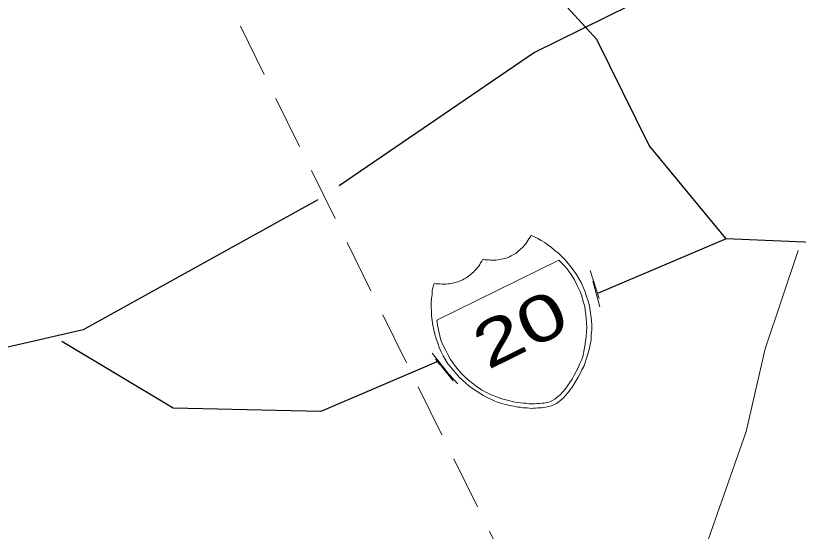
# Model space of a CAD drawing. Extents: x 2356606 to 2371222, y 6973096 to 6982644.
# Drawn here: x 2370773.7 to 2370861.3, y 6980289.2 to 6980347 of the extents above; entities that cross this region are included whole.
import ezdxf

# ---------------------------------------------------------------- set-up
doc = ezdxf.new("R2010")
doc.units = 0
doc.header["$LTSCALE"] = 2
doc.linetypes.add('MEDIUM_DASHED', pattern=[4.5, 3, -1.5])
doc.layers.add('62', color=7, linetype='Continuous', lineweight=13)
doc.layers.add('63', color=7, linetype='Continuous', lineweight=13)

msp = doc.modelspace()

# ---------------------------------------------------------------- linework, layer by layer
at = {"layer": '62', "linetype": 'MEDIUM_DASHED'}
msp.add_line((2370774.944, 6980394.196), (2370857.153, 6980227.678), dxfattribs=at)
at = {"layer": '62', "lineweight": 25}
msp.add_line((2370853.225, 6980321.969), (2370838.852, 6980315.852), dxfattribs=at)
at = {"layer": '62'}
for p, q in [((2370838.029, 6980318.432), (2370839.029, 6980315.29)), ((2370838.314, 6980317.245), (2370839.095, 6980314.393)), ((2370820.312, 6980309.186), (2370822.081, 6980306.974)), ((2370820.701, 6980308.55), (2370822.689, 6980306.095)), ((2370820.808, 6980308.329), (2370823.189, 6980305.741))]:
    msp.add_line(p, q, dxfattribs=at)
at = {"layer": '62', "lineweight": 25}
for points in [[(2371011.483, 6980396.661), (2371005.138, 6980391.825), (2370996.569, 6980386.616), (2370984.445, 6980379.452), (2370975.486, 6980375.033), (2370969.457, 6980371.078), (2370966.224, 6980366.347), (2370958.11, 6980360.159), (2370945.05, 6980354.893), (2370933.131, 6980350.014), (2370920.141, 6980344.556), (2370901.53, 6980332.234), (2370881.498, 6980325.485), (2370864.621, 6980321.497), (2370853.225, 6980321.969), (2370844.613, 6980332.451), (2370838.758, 6980344.313), (2370834.175, 6980349.329), (2370834.503, 6980359.904)], [(2370856.753, 6980352.442), (2370850.968, 6980349.159), (2370842.46, 6980348.097), (2370831.786, 6980342.831), (2370809.931, 6980327.928)], [(2370807.529, 6980326.342), (2370781.257, 6980311.796), (2370761.933, 6980307.378), (2370746.638, 6980307.707), (2370731.564, 6980303.779), (2370725.833, 6980299.271)], [(2370821.03, 6980308.287), (2370807.849, 6980302.659), (2370791.334, 6980303.02), (2370778.847, 6980310.48)]]:
    msp.add_lwpolyline(points, dxfattribs=at)
at = {"layer": '62'}
for points in [[(2370826.864, 6980319.599), (2370827.065, 6980319.598), (2370827.286, 6980319.606), (2370827.457, 6980319.616), (2370827.68, 6980319.626), (2370827.881, 6980319.675), (2370828.073, 6980319.693), (2370828.244, 6980319.754), (2370828.443, 6980319.802), (2370828.627, 6980319.84), (2370828.816, 6980319.909), (2370828.979, 6980319.989), (2370829.161, 6980320.082), (2370829.323, 6980320.161), (2370829.484, 6980320.241), (2370829.677, 6980320.361), (2370829.798, 6980320.469), (2370829.939, 6980320.59), (2370830.112, 6980320.7), (2370830.263, 6980320.85), (2370830.406, 6980320.971), (2370830.546, 6980321.14), (2370830.678, 6980321.279), (2370830.798, 6980321.439), (2370830.922, 6980321.602), (2370831.032, 6980321.783), (2370831.163, 6980321.973), (2370831.296, 6980322.165), (2370831.398, 6980322.365), (2370831.779, 6980322.203), (2370832.14, 6980322.027), (2370832.532, 6980321.794), (2370832.923, 6980321.561), (2370833.304, 6980321.294), (2370833.696, 6980321.012), (2370834.076, 6980320.698), (2370834.456, 6980320.384), (2370834.847, 6980319.999), (2370835.205, 6980319.625), (2370835.549, 6980319.241), (2370835.878, 6980318.828), (2370836.188, 6980318.402), (2370836.497, 6980317.979), (2370836.736, 6980317.545), (2370837.016, 6980317.081), (2370837.215, 6980316.576), (2370837.453, 6980316.042), (2370837.612, 6980315.516), (2370837.79, 6980315.004), (2370837.95, 6980314.481), (2370838.025, 6980313.916), (2370838.103, 6980313.402), (2370838.17, 6980312.859), (2370838.189, 6980312.314), (2370838.185, 6980311.762), (2370838.144, 6980311.24), (2370838.11, 6980310.695), (2370838.008, 6980310.142), (2370837.893, 6980309.611), (2370837.75, 6980309.087), (2370837.575, 6980308.525), (2370837.443, 6980308.133), (2370837.298, 6980307.711), (2370837.095, 6980307.31), (2370836.913, 6980306.919), (2370836.688, 6980306.507), (2370836.454, 6980306.115), (2370836.233, 6980305.754), (2370836.008, 6980305.391), (2370835.764, 6980305.072), (2370835.521, 6980304.751), (2370835.268, 6980304.45), (2370835.006, 6980304.171), (2370834.753, 6980303.971), (2370834.51, 6980303.748), (2370834.248, 6980303.571), (2370834.018, 6980303.431)], [(2370861.286, 6980320.676), (2370857.617, 6980309.659), (2370855.496, 6980300.434), (2370849.491, 6980283.413), (2370845.004, 6980266.221)], [(2370834.018, 6980303.431), (2370833.843, 6980303.37), (2370833.703, 6980303.301), (2370833.521, 6980303.262), (2370833.372, 6980303.213), (2370833.188, 6980303.174), (2370833.007, 6980303.133), (2370832.776, 6980303.095), (2370832.565, 6980303.067), (2370832.365, 6980303.066), (2370832.142, 6980303.057), (2370831.9, 6980303.04), (2370831.679, 6980303.031), (2370831.437, 6980303.012), (2370831.229, 6980303.032), (2370830.966, 6980303.054), (2370830.713, 6980303.056), (2370830.472, 6980303.087), (2370830.2, 6980303.128), (2370829.961, 6980303.16), (2370829.72, 6980303.191), (2370829.468, 6980303.242), (2370829.216, 6980303.295), (2370828.964, 6980303.345), (2370828.733, 6980303.406), (2370828.481, 6980303.46), (2370828.25, 6980303.521), (2370828.009, 6980303.603), (2370827.798, 6980303.674), (2370827.537, 6980303.746), (2370827.327, 6980303.816), (2370827.126, 6980303.92), (2370826.895, 6980304.031), (2370826.492, 6980304.233), (2370826.052, 6980304.469), (2370825.651, 6980304.721), (2370825.249, 6980304.974), (2370824.839, 6980305.249), (2370824.448, 6980305.532), (2370824.077, 6980305.827), (2370823.726, 6980306.181), (2370823.366, 6980306.505), (2370823.035, 6980306.868), (2370822.725, 6980307.243), (2370822.415, 6980307.617), (2370822.096, 6980308.011), (2370821.836, 6980308.433), (2370821.555, 6980308.898), (2370821.319, 6980309.333), (2370821.118, 6980309.838), (2370820.941, 6980310.301), (2370820.771, 6980310.795), (2370820.624, 6980311.3), (2370820.495, 6980311.811), (2370820.395, 6980312.316), (2370820.318, 6980312.829), (2370820.232, 6980313.364), (2370820.235, 6980313.865), (2370820.218, 6980314.361), (2370820.23, 6980314.842), (2370820.25, 6980315.307), (2370820.322, 6980315.768), (2370820.335, 6980316.202), (2370820.438, 6980316.604), (2370820.54, 6980317.006), (2370820.761, 6980316.966), (2370820.994, 6980316.954), (2370821.225, 6980316.943), (2370821.438, 6980316.921), (2370821.658, 6980316.929), (2370821.859, 6980316.928), (2370822.07, 6980316.956), (2370822.273, 6980316.957), (2370822.452, 6980316.996), (2370822.644, 6980317.014), (2370822.836, 6980317.085), (2370823.018, 6980317.123), (2370823.24, 6980317.184), (2370823.39, 6980317.233), (2370823.551, 6980317.313), (2370823.755, 6980317.411), (2370823.915, 6980317.493), (2370824.076, 6980317.57), (2370824.249, 6980317.68), (2370824.39, 6980317.8), (2370824.53, 6980317.919), (2370824.683, 6980318.021), (2370824.856, 6980318.18), (2370824.997, 6980318.301), (2370825.117, 6980318.461), (2370825.249, 6980318.6), (2370825.39, 6980318.771), (2370825.533, 6980318.942), (2370825.644, 6980319.124), (2370825.755, 6980319.305), (2370825.868, 6980319.484), (2370825.989, 6980319.696), (2370826.21, 6980319.653), (2370826.421, 6980319.632), (2370826.652, 6980319.621), (2370826.864, 6980319.599)]]:
    msp.add_lwpolyline(points, dxfattribs=at)
msp.add_lwpolyline([(2370834.514, 6980319.607), (2370820.853, 6980312.865), (2370820.871, 6980312.625), (2370820.92, 6980312.323), (2370820.979, 6980312), (2370821.079, 6980311.598), (2370821.176, 6980311.144), (2370821.314, 6980310.662), (2370821.524, 6980310.137), (2370821.801, 6980309.571), (2370822.07, 6980309.025), (2370822.389, 6980308.483), (2370822.747, 6980307.957), (2370823.14, 6980307.473), (2370823.549, 6980306.996), (2370823.95, 6980306.591), (2370824.391, 6980306.158), (2370824.873, 6980305.792), (2370825.351, 6980305.428), (2370825.844, 6980305.094), (2370826.396, 6980304.788), (2370826.929, 6980304.523), (2370827.519, 6980304.29), (2370828.121, 6980304.085), (2370828.705, 6980303.92), (2370829.329, 6980303.776), (2370829.619, 6980303.694), (2370829.93, 6980303.674), (2370830.233, 6980303.62), (2370830.565, 6980303.608), (2370830.857, 6980303.578), (2370831.179, 6980303.535), (2370831.482, 6980303.536), (2370831.782, 6980303.532), (2370832.074, 6980303.552), (2370832.346, 6980303.561), (2370832.64, 6980303.579), (2370832.879, 6980303.597), (2370833.141, 6980303.677), (2370833.372, 6980303.714), (2370833.585, 6980303.793), (2370833.798, 6980303.876), (2370834.059, 6980304.053), (2370834.373, 6980304.285), (2370834.646, 6980304.544), (2370834.939, 6980304.863), (2370835.222, 6980305.154), (2370835.484, 6980305.536), (2370835.729, 6980305.907), (2370835.994, 6980306.287), (2370836.238, 6980306.711), (2370836.453, 6980307.142), (2370836.655, 6980307.542), (2370836.828, 6980307.955), (2370837.011, 6980308.347), (2370837.154, 6980308.717), (2370837.266, 6980309.101), (2370837.318, 6980309.402), (2370837.432, 6980309.985), (2370837.494, 6980310.518), (2370837.558, 6980311.049), (2370837.591, 6980311.592), (2370837.626, 6980312.086), (2370837.607, 6980312.581), (2370837.578, 6980313.042), (2370837.523, 6980313.516), (2370837.463, 6980313.989), (2370837.405, 6980314.41), (2370837.285, 6980314.855), (2370837.157, 6980315.269), (2370837.029, 6980315.682), (2370836.879, 6980316.085), (2370836.712, 6980316.477), (2370836.532, 6980316.842), (2370836.254, 6980317.406), (2370835.963, 6980317.892), (2370835.664, 6980318.294), (2370835.404, 6980318.667), (2370835.124, 6980318.981), (2370834.884, 6980319.214), (2370834.674, 6980319.438)], close=True, dxfattribs=at)
at = {"layer": '63', "linetype": 'MEDIUM_DASHED'}
msp.add_line((2370774.944, 6980394.196), (2370857.153, 6980227.678), dxfattribs=at)
at = {"layer": '63', "lineweight": 25}
msp.add_line((2370853.225, 6980321.969), (2370838.852, 6980315.852), dxfattribs=at)
at = {"layer": '63'}
for p, q in [((2370838.029, 6980318.432), (2370839.029, 6980315.29)), ((2370838.314, 6980317.245), (2370839.095, 6980314.393)), ((2370820.312, 6980309.186), (2370822.081, 6980306.974)), ((2370820.701, 6980308.55), (2370822.689, 6980306.095)), ((2370820.808, 6980308.329), (2370823.189, 6980305.741))]:
    msp.add_line(p, q, dxfattribs=at)
at = {"layer": '63', "lineweight": 25}
for points in [[(2371011.483, 6980396.661), (2371005.138, 6980391.825), (2370996.569, 6980386.616), (2370984.445, 6980379.452), (2370975.486, 6980375.033), (2370969.457, 6980371.078), (2370966.224, 6980366.347), (2370958.11, 6980360.159), (2370945.05, 6980354.893), (2370933.131, 6980350.014), (2370920.141, 6980344.556), (2370901.53, 6980332.234), (2370881.498, 6980325.485), (2370864.621, 6980321.497), (2370853.225, 6980321.969), (2370844.613, 6980332.451), (2370838.758, 6980344.313), (2370834.175, 6980349.329), (2370834.503, 6980359.904)], [(2370856.753, 6980352.442), (2370850.968, 6980349.159), (2370842.46, 6980348.097), (2370831.786, 6980342.831), (2370809.931, 6980327.928)], [(2370807.529, 6980326.342), (2370781.257, 6980311.796), (2370761.933, 6980307.378), (2370746.638, 6980307.707), (2370731.564, 6980303.779), (2370725.833, 6980299.271)], [(2370821.03, 6980308.287), (2370807.849, 6980302.659), (2370791.334, 6980303.02), (2370778.847, 6980310.48)]]:
    msp.add_lwpolyline(points, dxfattribs=at)
at = {"layer": '63'}
for points in [[(2370826.864, 6980319.599), (2370827.065, 6980319.598), (2370827.286, 6980319.606), (2370827.457, 6980319.616), (2370827.68, 6980319.626), (2370827.881, 6980319.675), (2370828.073, 6980319.693), (2370828.244, 6980319.754), (2370828.443, 6980319.802), (2370828.627, 6980319.84), (2370828.816, 6980319.909), (2370828.979, 6980319.989), (2370829.161, 6980320.082), (2370829.323, 6980320.161), (2370829.484, 6980320.241), (2370829.677, 6980320.361), (2370829.798, 6980320.469), (2370829.939, 6980320.59), (2370830.112, 6980320.7), (2370830.263, 6980320.85), (2370830.406, 6980320.971), (2370830.546, 6980321.14), (2370830.678, 6980321.279), (2370830.798, 6980321.439), (2370830.922, 6980321.602), (2370831.032, 6980321.783), (2370831.163, 6980321.973), (2370831.296, 6980322.165), (2370831.398, 6980322.365), (2370831.779, 6980322.203), (2370832.14, 6980322.027), (2370832.532, 6980321.794), (2370832.923, 6980321.561), (2370833.304, 6980321.294), (2370833.696, 6980321.012), (2370834.076, 6980320.698), (2370834.456, 6980320.384), (2370834.847, 6980319.999), (2370835.205, 6980319.625), (2370835.549, 6980319.241), (2370835.878, 6980318.828), (2370836.188, 6980318.402), (2370836.497, 6980317.979), (2370836.736, 6980317.545), (2370837.016, 6980317.081), (2370837.215, 6980316.576), (2370837.453, 6980316.042), (2370837.612, 6980315.516), (2370837.79, 6980315.004), (2370837.95, 6980314.481), (2370838.025, 6980313.916), (2370838.103, 6980313.402), (2370838.17, 6980312.859), (2370838.189, 6980312.314), (2370838.185, 6980311.762), (2370838.144, 6980311.24), (2370838.11, 6980310.695), (2370838.008, 6980310.142), (2370837.893, 6980309.611), (2370837.75, 6980309.087), (2370837.575, 6980308.525), (2370837.443, 6980308.133), (2370837.298, 6980307.711), (2370837.095, 6980307.31), (2370836.913, 6980306.919), (2370836.688, 6980306.507), (2370836.454, 6980306.115), (2370836.233, 6980305.754), (2370836.008, 6980305.391), (2370835.764, 6980305.072), (2370835.521, 6980304.751), (2370835.268, 6980304.45), (2370835.006, 6980304.171), (2370834.753, 6980303.971), (2370834.51, 6980303.748), (2370834.248, 6980303.571), (2370834.018, 6980303.431)], [(2370861.286, 6980320.676), (2370857.617, 6980309.659), (2370855.496, 6980300.434), (2370849.491, 6980283.413), (2370845.004, 6980266.221)], [(2370834.018, 6980303.431), (2370833.843, 6980303.37), (2370833.703, 6980303.301), (2370833.521, 6980303.262), (2370833.372, 6980303.213), (2370833.188, 6980303.174), (2370833.007, 6980303.133), (2370832.776, 6980303.095), (2370832.565, 6980303.067), (2370832.365, 6980303.066), (2370832.142, 6980303.057), (2370831.9, 6980303.04), (2370831.679, 6980303.031), (2370831.437, 6980303.012), (2370831.229, 6980303.032), (2370830.966, 6980303.054), (2370830.713, 6980303.056), (2370830.472, 6980303.087), (2370830.2, 6980303.128), (2370829.961, 6980303.16), (2370829.72, 6980303.191), (2370829.468, 6980303.242), (2370829.216, 6980303.295), (2370828.964, 6980303.345), (2370828.733, 6980303.406), (2370828.481, 6980303.46), (2370828.25, 6980303.521), (2370828.009, 6980303.603), (2370827.798, 6980303.674), (2370827.537, 6980303.746), (2370827.327, 6980303.816), (2370827.126, 6980303.92), (2370826.895, 6980304.031), (2370826.492, 6980304.233), (2370826.052, 6980304.469), (2370825.651, 6980304.721), (2370825.249, 6980304.974), (2370824.839, 6980305.249), (2370824.448, 6980305.532), (2370824.077, 6980305.827), (2370823.726, 6980306.181), (2370823.366, 6980306.505), (2370823.035, 6980306.868), (2370822.725, 6980307.243), (2370822.415, 6980307.617), (2370822.096, 6980308.011), (2370821.836, 6980308.433), (2370821.555, 6980308.898), (2370821.319, 6980309.333), (2370821.118, 6980309.838), (2370820.941, 6980310.301), (2370820.771, 6980310.795), (2370820.624, 6980311.3), (2370820.495, 6980311.811), (2370820.395, 6980312.316), (2370820.318, 6980312.829), (2370820.232, 6980313.364), (2370820.235, 6980313.865), (2370820.218, 6980314.361), (2370820.23, 6980314.842), (2370820.25, 6980315.307), (2370820.322, 6980315.768), (2370820.335, 6980316.202), (2370820.438, 6980316.604), (2370820.54, 6980317.006), (2370820.761, 6980316.966), (2370820.994, 6980316.954), (2370821.225, 6980316.943), (2370821.438, 6980316.921), (2370821.658, 6980316.929), (2370821.859, 6980316.928), (2370822.07, 6980316.956), (2370822.273, 6980316.957), (2370822.452, 6980316.996), (2370822.644, 6980317.014), (2370822.836, 6980317.085), (2370823.018, 6980317.123), (2370823.24, 6980317.184), (2370823.39, 6980317.233), (2370823.551, 6980317.313), (2370823.755, 6980317.411), (2370823.915, 6980317.493), (2370824.076, 6980317.57), (2370824.249, 6980317.68), (2370824.39, 6980317.8), (2370824.53, 6980317.919), (2370824.683, 6980318.021), (2370824.856, 6980318.18), (2370824.997, 6980318.301), (2370825.117, 6980318.461), (2370825.249, 6980318.6), (2370825.39, 6980318.771), (2370825.533, 6980318.942), (2370825.644, 6980319.124), (2370825.755, 6980319.305), (2370825.868, 6980319.484), (2370825.989, 6980319.696), (2370826.21, 6980319.653), (2370826.421, 6980319.632), (2370826.652, 6980319.621), (2370826.864, 6980319.599)]]:
    msp.add_lwpolyline(points, dxfattribs=at)
msp.add_lwpolyline([(2370834.514, 6980319.607), (2370820.853, 6980312.865), (2370820.871, 6980312.625), (2370820.92, 6980312.323), (2370820.979, 6980312), (2370821.079, 6980311.598), (2370821.176, 6980311.144), (2370821.314, 6980310.662), (2370821.524, 6980310.137), (2370821.801, 6980309.571), (2370822.07, 6980309.025), (2370822.389, 6980308.483), (2370822.747, 6980307.957), (2370823.14, 6980307.473), (2370823.549, 6980306.996), (2370823.95, 6980306.591), (2370824.391, 6980306.158), (2370824.873, 6980305.792), (2370825.351, 6980305.428), (2370825.844, 6980305.094), (2370826.396, 6980304.788), (2370826.929, 6980304.523), (2370827.519, 6980304.29), (2370828.121, 6980304.085), (2370828.705, 6980303.92), (2370829.329, 6980303.776), (2370829.619, 6980303.694), (2370829.93, 6980303.674), (2370830.233, 6980303.62), (2370830.565, 6980303.608), (2370830.857, 6980303.578), (2370831.179, 6980303.535), (2370831.482, 6980303.536), (2370831.782, 6980303.532), (2370832.074, 6980303.552), (2370832.346, 6980303.561), (2370832.64, 6980303.579), (2370832.879, 6980303.597), (2370833.141, 6980303.677), (2370833.372, 6980303.714), (2370833.585, 6980303.793), (2370833.798, 6980303.876), (2370834.059, 6980304.053), (2370834.373, 6980304.285), (2370834.646, 6980304.544), (2370834.939, 6980304.863), (2370835.222, 6980305.154), (2370835.484, 6980305.536), (2370835.729, 6980305.907), (2370835.994, 6980306.287), (2370836.238, 6980306.711), (2370836.453, 6980307.142), (2370836.655, 6980307.542), (2370836.828, 6980307.955), (2370837.011, 6980308.347), (2370837.154, 6980308.717), (2370837.266, 6980309.101), (2370837.318, 6980309.402), (2370837.432, 6980309.985), (2370837.494, 6980310.518), (2370837.558, 6980311.049), (2370837.591, 6980311.592), (2370837.626, 6980312.086), (2370837.607, 6980312.581), (2370837.578, 6980313.042), (2370837.523, 6980313.516), (2370837.463, 6980313.989), (2370837.405, 6980314.41), (2370837.285, 6980314.855), (2370837.157, 6980315.269), (2370837.029, 6980315.682), (2370836.879, 6980316.085), (2370836.712, 6980316.477), (2370836.532, 6980316.842), (2370836.254, 6980317.406), (2370835.963, 6980317.892), (2370835.664, 6980318.294), (2370835.404, 6980318.667), (2370835.124, 6980318.981), (2370834.884, 6980319.214), (2370834.674, 6980319.438)], close=True, dxfattribs=at)

# ---------------------------------------------------------------- texts
at = {"layer": '62', "width": 1.4}
msp.add_text('20', height=5.099, rotation=26.268, dxfattribs=at).set_placement((2370826.548, 6980307.273))
at = {"layer": '63', "width": 1.4}
msp.add_text('20', height=5.099, rotation=26.268, dxfattribs=at).set_placement((2370826.548, 6980307.273))

doc.saveas('drawing.dxf')
